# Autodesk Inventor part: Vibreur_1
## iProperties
Created: 2010-07
Part Number: Vibreur_1
Document SubType Name: Modeling
Designer: eric
Density: 1 g/cm^3
Mass: 0.379556 g
Surface Area: 3.25032 cm^2
Volume: 0.379556 cm^3
Author: eric
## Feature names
1. Revolution1
2. Hole1
3. Fillet1
